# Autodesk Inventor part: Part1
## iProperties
Created: 2018-06
Part Number: Part1
Document SubType Name: Modeling
Designer: M.Shelton
Density: 1 g/cm^3
Author: M.Shelton
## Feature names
1. Extrusion1
2. Chamfer7
3. Fillet1
4. Fillet2
5. Fillet3
6. Fillet4
7. Fillet5
8. Fillet6
9. Extrusion4
10. Fillet7
11. Fillet8
12. Fillet9
13. Fillet10
14. Extrusion5
15. Extrusion6
16. Extrusion8
17. Chamfer8
18. Chamfer9
19. Chamfer10
20. Chamfer11
21. Chamfer12
22. Chamfer13
23. Chamfer14
24. Chamfer15
25. Chamfer16
26. Chamfer17
27. Fillet14
28. Fillet15
